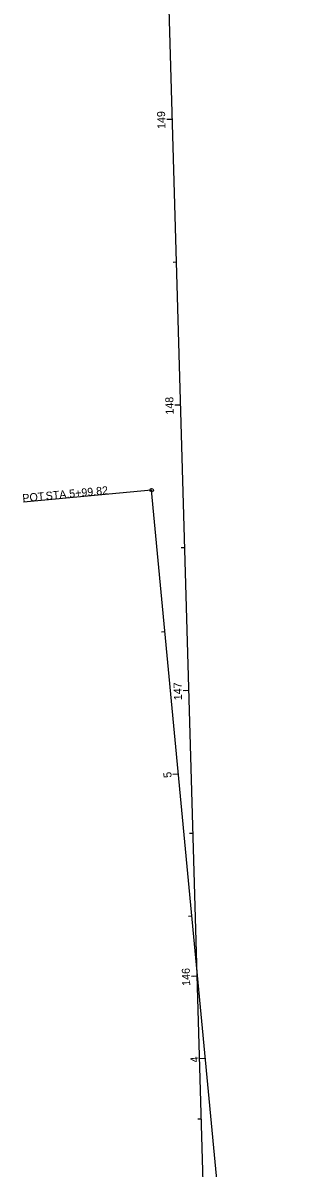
# Model space of a CAD drawing. Extents: x 177110 to 177558, y 286252 to 294117.
# Drawn here: x 177232.9 to 177334.5, y 290268.4 to 290669.2 of the extents above; entities that cross this region are included whole.
import ezdxf

# ---------------------------------------------------------------- set-up
doc = ezdxf.new("R2010")
doc.units = 0
for name, color, linetype in [('GE_X_Alignment', 7, 'Continuous'), ('GE_X_Alignment_100_Cardinal_Points', 7, 'Continuous'), ('GE_X_Alignment_100_Stations', 7, 'Continuous'), ('GE_X_Alignment_500_Stations', 7, 'Continuous'), ('RW_X_CL', 7, 'Continuous'), ('RW_X_CL_100_Stations', 7, 'Continuous'), ('SC_Scratch1', 7, 'Continuous')]:
    doc.layers.add(name, color=color, linetype=linetype)

msp = doc.modelspace()

# ---------------------------------------------------------------- linework, layer by layer
at = {"layer": 'GE_X_Alignment'}
msp.add_line((177334.49, 289908.55), (177277.99, 290505.7), dxfattribs=at)
at = {"layer": 'GE_X_Alignment_100_Cardinal_Points'}
msp.add_line((177277.99, 290505.7), (177233.19, 290501.47), dxfattribs=at)
msp.add_circle((177277.99, 290505.7), 0.6, dxfattribs=at)
at = {"layer": 'GE_X_Alignment_100_Stations'}
for p, q in [((177282.69, 290456.11), (177281.49, 290455.99)), ((177287.4, 290406.33), (177285.41, 290406.14)), ((177292.11, 290356.55), (177290.91, 290356.44)), ((177296.82, 290306.77), (177294.82, 290306.59))]:
    msp.add_line(p, q, dxfattribs=at)
at = {"layer": 'GE_X_Alignment_500_Stations'}
for p, q in [((177285.25, 290635.42), (177284.05, 290635.38)), ((177288.13, 290535.46), (177286.93, 290535.42)), ((177291.01, 290435.5), (177289.81, 290435.47)), ((177293.89, 290335.54), (177292.7, 290335.51))]:
    msp.add_line(p, q, dxfattribs=at)
at = {"layer": 'RW_X_CL'}
msp.add_line((177299.88, 290127.96), (177261.21, 291468.79), dxfattribs=at)
at = {"layer": 'RW_X_CL_100_Stations'}
for p, q in [((177285.25, 290635.42), (177283.25, 290635.36)), ((177286.69, 290585.44), (177285.49, 290585.4)), ((177288.13, 290535.46), (177286.13, 290535.4)), ((177289.57, 290485.48), (177288.37, 290485.44)), ((177291.01, 290435.5), (177289.01, 290435.44)), ((177292.45, 290385.52), (177291.25, 290385.49)), ((177293.89, 290335.54), (177291.9, 290335.48)), ((177295.34, 290285.56), (177294.14, 290285.53))]:
    msp.add_line(p, q, dxfattribs=at)
at = {"layer": 'SC_Scratch1'}
msp.add_line((177303.45, 290004.39), (177261.21, 291468.79), dxfattribs=at)

# ---------------------------------------------------------------- texts
at = {"layer": 'GE_X_Alignment_100_Cardinal_Points'}
for s, p in [('POT', (177232.88, 290501.47)), (' STA. ', (177239.98, 290502.14)), ('5+99.82', (177249.26, 290503.02))]:
    msp.add_text(s, height=2.8, rotation=5.405, dxfattribs=at).set_placement(p)
at = {"layer": 'GE_X_Alignment_100_Stations'}
for s, p in [('5', (177285, 290405.13)), ('4', (177294.43, 290305.5))]:
    msp.add_text(s, height=2.8, rotation=95.405, dxfattribs=at).set_placement(p)
at = {"layer": 'RW_X_CL_100_Stations'}
for s, p in [('149', (177282.84, 290632.12)), ('148', (177285.72, 290532.14)), ('147', (177288.61, 290432.19)), ('146', (177291.49, 290332.22))]:
    msp.add_text(s, height=2.8, rotation=91.6519, dxfattribs=at).set_placement(p)

doc.saveas('drawing.dxf')
